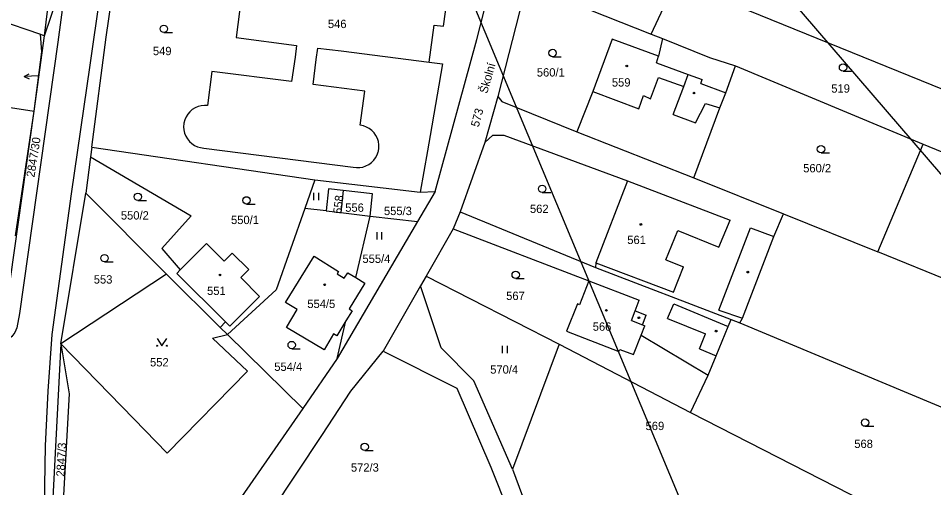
# Model space of a CAD drawing. Extents: x -558358 to -557517, y -1073785 to -1073189.
# Drawn here: x -558184.5 to -557998, y -1073651.5 to -1073555.9 of the extents above; entities that cross this region are included whole.
import ezdxf

# ---------------------------------------------------------------- set-up
doc = ezdxf.new("R2010")
doc.units = 0
for name, color, linetype in [('Hranice parcel', 7, 'Continuous'), ('Parcelní čísla', 7, 'Continuous'), ('Pop  PČ popisy', 7, 'Continuous'), ('Vnitřní kresba', 7, 'Continuous'), ('Vrstva 28', 7, 'Continuous'), ('Značky budov', 7, 'Continuous'), ('Značky kultur', 7, 'Continuous')]:
    doc.layers.add(name, color=color, linetype=linetype)

msp = doc.modelspace()

# ---------------------------------------------------------------- linework, layer by layer
at = {"layer": 'Hranice parcel'}
for p, q in [((-558179.14, -1073559.41), (-558177.37, -1073544.49)), ((-558179.14, -1073559.41), (-558174.43, -1073545.49)), ((-558174.43, -1073545.49), (-558176.44, -1073560.75)), ((-558210.55, -1073548.74), (-558179.99, -1073559.12)), ((-558080.96, -1073549.01), (-558086.83, -1073571.83)), ((-558080.96, -1073549.01), (-558055.56, -1073559.09)), ((-558181.3, -1073574.78), (-558179.14, -1073559.41)), ((-558179.99, -1073559.12), (-558179.14, -1073559.41)), ((-558055.56, -1073559.09), (-558053.26, -1073559.97)), ((-558038.36, -1073565.55), (-558000.16, -1073581.51)), ((-558219.67, -1073569.09), (-558181.3, -1073574.78)), ((-558086.83, -1073571.83), (-558089.47, -1073581.15)), ((-558187.72, -1073620.52), (-558181.3, -1073574.78)), ((-558185.06, -1073600.21), (-558181.3, -1073574.78)), ((-558070.72, -1073578.99), (-558046.87, -1073588.38)), ((-558089.47, -1073581.15), (-558094.5, -1073595.31)), ((-558009.36, -1073603.49), (-558000.16, -1073581.51)), ((-558000.16, -1073581.51), (-557977.41, -1073591.02)), ((-558169.56, -1073582.12), (-558169.81, -1073584.08)), ((-558169.56, -1073582.12), (-558124.1, -1073588.8)), ((-558146.72, -1073582.31), (-558116.26, -1073586.22)), ((-558169.81, -1073584.08), (-558170.74, -1073591.52)), ((-558124.1, -1073588.8), (-558126.13, -1073594.62)), ((-558124.1, -1073588.8), (-558102.62, -1073591.27)), ((-558046.87, -1073588.38), (-558028.58, -1073595.68)), ((-558118.29, -1073590.98), (-558118.81, -1073595.47)), ((-558099.6, -1073591.18), (-558103.17, -1073597.28)), ((-558102.62, -1073591.27), (-558099.6, -1073591.18)), ((-558175.82, -1073622.18), (-558170.74, -1073591.52)), ((-558154.32, -1073608.02), (-558170.74, -1073591.52)), ((-558121.8, -1073595.12), (-558126.13, -1073594.62)), ((-558121.8, -1073595.12), (-558118.81, -1073595.47)), ((-558118.81, -1073595.47), (-558112.83, -1073596.16)), ((-558115.73, -1073608.72), (-558112.83, -1073596.16)), ((-558112.83, -1073596.16), (-558103.17, -1073597.28)), ((-558094.5, -1073595.31), (-558095.93, -1073598.78)), ((-558094.5, -1073595.31), (-558066.88, -1073606.68)), ((-558028.58, -1073595.68), (-558009.36, -1073603.49)), ((-558103.17, -1073597.28), (-558119.53, -1073625.2)), ((-558095.93, -1073598.78), (-558101.44, -1073608.4)), ((-558155.28, -1073602.76), (-558151.5, -1073607.15)), ((-557981.3, -1073614.89), (-558009.36, -1073603.49)), ((-558154.32, -1073608.02), (-558175.82, -1073622.18)), ((-558143.35, -1073618.87), (-558154.32, -1073608.02)), ((-558066.88, -1073606.68), (-558039.3, -1073617.26)), ((-558101.44, -1073608.4), (-558102.56, -1073610.37)), ((-558101.44, -1073608.4), (-558074.34, -1073622.3)), ((-558102.56, -1073610.37), (-558110.18, -1073623.69)), ((-558039.3, -1073617.26), (-558037.5, -1073617.95)), ((-558142.28, -1073617.72), (-558143.35, -1073618.87)), ((-558141.92, -1073620.28), (-558143.35, -1073618.87)), ((-558119.53, -1073625.2), (-558117.76, -1073617.53)), ((-558126.57, -1073635.37), (-558141.92, -1073620.28)), ((-558074.34, -1073622.3), (-558083.83, -1073647.78)), ((-558074.34, -1073622.3), (-558047.53, -1073636.2)), ((-558119.53, -1073625.2), (-558126.57, -1073635.37)), ((-558047.53, -1073636.2), (-558043.97, -1073628.57)), ((-558083.83, -1073647.78), (-558091.67, -1073629.76)), ((-558126.57, -1073635.37), (-558152.59, -1073672.96)), ((-558047.53, -1073636.2), (-557987.38, -1073666.93)), ((-558083.83, -1073647.78), (-558081.75, -1073653.27))]:
    msp.add_line(p, q, dxfattribs=at)
for points in [[(-558086.19, -1073392.25), (-558100.56, -1073410.01), (-558117.51, -1073431.08), (-558131.78, -1073449.27), (-558138.48, -1073457.68), (-558143.38, -1073464.02), (-558146.99, -1073468.89), (-558150.46, -1073473.83), (-558152.02, -1073476.41), (-558154.26, -1073480.97), (-558156.46, -1073486.6), (-558158.91, -1073494.31), (-558160.3, -1073500.48), (-558162.16, -1073510.4), (-558165.76, -1073536.46), (-558169.94, -1073565.43), (-558173.74, -1073591.61), (-558177.66, -1073620.33), (-558178.51, -1073631.87), (-558179.02, -1073643), (-558179.24, -1073655.12), (-558179.45, -1073666.94), (-558179.49, -1073675.4)], [(-558169.56, -1073582.12), (-558166.59, -1073559.69), (-558162.5, -1073531.6)], [(-558137.04, -1073535.13), (-558138.34, -1073545.94), (-558140.1, -1073559.78), (-558127.81, -1073561.38), (-558128.13, -1073563.82), (-558128.85, -1073568.77)], [(-558099.6, -1073591.18), (-558091.09, -1073560.2), (-558086.54, -1073542.34)], [(-558055.56, -1073559.09), (-558052.02, -1073551.52), (-558051, -1073549.15), (-558050.57, -1073548.21)], [(-557977.41, -1073591.02), (-557981.5, -1073577.12), (-557984.25, -1073575.17), (-558047.33, -1073549.53)], [(-558181.3, -1073574.78), (-558179.75, -1073562.68), (-558179.99, -1073559.12)], [(-558176.44, -1073560.75), (-558184.28, -1073616.01), (-558184.84, -1073618.94), (-558185.24, -1073619.89), (-558185.86, -1073620.72), (-558186.64, -1073621.38)], [(-558053.26, -1073559.97), (-558054.09, -1073563.56), (-558063.5, -1073560.11), (-558067.45, -1073570.76), (-558070.72, -1073578.99)], [(-558053.26, -1073559.97), (-558043.68, -1073563.84), (-558038.36, -1073565.55)], [(-558124.4, -1073569.34), (-558123.84, -1073564.23), (-558123.49, -1073561.94), (-558118.73, -1073562.49), (-558100.77, -1073564.79), (-558098.05, -1073565.18), (-558100.59, -1073579.72), (-558101.17, -1073582.9), (-558102.62, -1073591.27)], [(-558128.85, -1073568.77), (-558145.05, -1073566.7), (-558145.94, -1073573.66)], [(-558046.87, -1073588.38), (-558041.59, -1073574.1), (-558040.35, -1073571.05), (-558038.36, -1073565.55)], [(-558114.83, -1073577.66), (-558113.93, -1073570.69), (-558124.4, -1073569.34)], [(-558086.83, -1073571.83), (-558085.98, -1073572.82), (-558070.72, -1073578.99)], [(-558145.94, -1073573.66), (-558146.6, -1073573.63), (-558147.25, -1073573.7), (-558147.89, -1073573.86), (-558148.5, -1073574.12), (-558149.06, -1073574.47), (-558149.56, -1073574.9), (-558149.98, -1073575.4), (-558150.33, -1073575.96), (-558150.59, -1073576.57), (-558150.76, -1073577.21), (-558150.78, -1073577.3), (-558150.83, -1073577.96), (-558150.78, -1073578.62), (-558150.63, -1073579.26), (-558150.39, -1073579.87), (-558150.06, -1073580.44), (-558149.64, -1073580.95), (-558149.15, -1073581.4), (-558148.6, -1073581.76), (-558148.01, -1073582.04), (-558147.37, -1073582.22), (-558146.72, -1073582.31)], [(-558116.26, -1073586.22), (-558115.61, -1073586.3), (-558114.95, -1073586.29), (-558114.3, -1073586.17), (-558113.68, -1073585.96), (-558113.09, -1073585.66), (-558112.56, -1073585.27), (-558112.09, -1073584.8), (-558111.7, -1073584.27), (-558111.4, -1073583.69), (-558111.18, -1073583.06), (-558111.15, -1073582.95), (-558111.05, -1073582.3), (-558111.05, -1073581.64), (-558111.15, -1073580.99), (-558111.35, -1073580.36), (-558111.64, -1073579.77), (-558112.02, -1073579.22), (-558112.47, -1073578.75), (-558112.99, -1073578.34), (-558113.57, -1073578.02), (-558114.19, -1073577.79), (-558114.83, -1073577.66)], [(-558089.47, -1073581.15), (-558087.83, -1073579.66), (-558085.58, -1073579.68), (-558060.36, -1073588.97), (-558066.81, -1073605.67), (-558066.88, -1073606.68)], [(-558169.81, -1073584.08), (-558149.27, -1073596.11), (-558155.28, -1073602.76)], [(-558118.29, -1073590.98), (-558121.28, -1073590.64), (-558121.8, -1073595.12)], [(-558112.83, -1073596.16), (-558112.31, -1073591.67), (-558118.29, -1073590.98)], [(-558126.13, -1073594.62), (-558131.94, -1073611.23), (-558141.92, -1073620.28)], [(-558037.5, -1073617.95), (-558036.99, -1073617), (-558030.56, -1073600.34), (-558028.58, -1073595.68)], [(-558095.93, -1073598.78), (-558068.28, -1073609.38), (-558070.18, -1073614.23), (-558070.6, -1073614.06), (-558072.8, -1073619.63), (-558062.12, -1073623.77), (-558061.94, -1073623.36), (-558059.17, -1073624.37), (-558057.59, -1073620.43), (-558043.97, -1073628.57)], [(-558142.28, -1073617.72), (-558141.4, -1073618.59), (-558135.35, -1073612.55), (-558139.15, -1073608.7), (-558137.51, -1073607.05), (-558140.91, -1073603.7), (-558142.57, -1073605.38), (-558146.16, -1073601.75), (-558151.5, -1073607.15)], [(-558117.76, -1073617.53), (-558119.58, -1073620.56), (-558120.26, -1073620.18), (-558122.2, -1073623.43), (-558129.88, -1073618.85), (-558127.67, -1073615.2), (-558130.05, -1073613.78), (-558124.22, -1073604.32), (-558119.25, -1073607.46), (-558119.52, -1073607.94), (-558118.12, -1073608.84), (-558117.4, -1073607.72), (-558115.73, -1073608.72)], [(-558151.5, -1073607.15), (-558152.22, -1073607.87), (-558142.28, -1073617.72)], [(-558115.73, -1073608.72), (-558113.89, -1073609.83), (-558117.1, -1073615.05), (-558116.51, -1073615.45), (-558117.76, -1073617.53)], [(-558091.67, -1073629.76), (-558098.34, -1073623.01), (-558102.56, -1073610.37)], [(-558043.97, -1073628.57), (-558042.35, -1073624.63), (-558039.87, -1073618.65), (-558039.3, -1073617.26)], [(-558037.5, -1073617.95), (-557968.93, -1073646.57), (-557957.49, -1073653.98)], [(-558175.82, -1073622.18), (-558161, -1073637.48), (-558154.2, -1073644.46), (-558137.82, -1073627.75), (-558144.92, -1073621.06), (-558141.92, -1073620.28)], [(-558175.82, -1073622.18), (-558177.63, -1073656.22), (-558176.05, -1073666.5)], [(-558175.82, -1073622.18), (-558174.18, -1073632.38), (-558176.05, -1073666.5)], [(-558143.16, -1073671.79), (-558122.68, -1073640.91), (-558116.74, -1073631.82), (-558110.18, -1073623.69)], [(-558110.18, -1073623.69), (-558095.16, -1073631.27), (-558088.2, -1073647.35), (-558084.61, -1073656.37)]]:
    msp.add_lwpolyline(points, dxfattribs=at)
at = {"layer": 'Pop  PČ popisy'}
for p, q in [((-558183.31, -1073567.74), (-558182.33, -1073567.19)), ((-558180.31, -1073567.58), (-558183.31, -1073567.74)), ((-558183.31, -1073567.74), (-558182.28, -1073568.19))]:
    msp.add_line(p, q, dxfattribs=at)
at = {"layer": 'Vnitřní kresba'}
for p, q in [((-558097.85, -1073557.5), (-558097.04, -1073551.46)), ((-558100.77, -1073564.79), (-558099.8, -1073557.24)), ((-558099.8, -1073557.24), (-558097.85, -1073557.5)), ((-558054.51, -1073564.95), (-558054.09, -1073563.56)), ((-558054.51, -1073564.95), (-558048, -1073567.3)), ((-558055.72, -1073572.3), (-558054.04, -1073567.93)), ((-558054.04, -1073567.93), (-558048.94, -1073569.79)), ((-558048.94, -1073569.79), (-558048, -1073567.3)), ((-558048, -1073567.3), (-558045.17, -1073568.34)), ((-558045.48, -1073569.18), (-558045.17, -1073568.34)), ((-558067.45, -1073570.76), (-558058.09, -1073574.3)), ((-558051.08, -1073575.44), (-558048.94, -1073569.79)), ((-558045.48, -1073569.18), (-558040.35, -1073571.05)), ((-558058.09, -1073574.3), (-558057.1, -1073571.59)), ((-558057.1, -1073571.59), (-558055.72, -1073572.3)), ((-558046.52, -1073577.2), (-558044.47, -1073573.2)), ((-558044.47, -1073573.2), (-558041.59, -1073574.1)), ((-558051.08, -1073575.44), (-558046.52, -1073577.2)), ((-558060.36, -1073588.97), (-558039.44, -1073597)), ((-558041.81, -1073602.48), (-558039.44, -1073597)), ((-558041.75, -1073615.33), (-558035.32, -1073598.58)), ((-558035.32, -1073598.58), (-558030.56, -1073600.34)), ((-558052.58, -1073605.08), (-558050.15, -1073599.12)), ((-558050.15, -1073599.12), (-558041.81, -1073602.48)), ((-558066.81, -1073605.67), (-558051.04, -1073611.69)), ((-558052.58, -1073605.08), (-558049.01, -1073606.53)), ((-558051.04, -1073611.69), (-558049.01, -1073606.53)), ((-558068.28, -1073609.38), (-558058.04, -1073613.34)), ((-558058.85, -1073615.47), (-558058.04, -1073613.34)), ((-558059.56, -1073617.45), (-558058.85, -1073615.47)), ((-558058.85, -1073615.47), (-558056.6, -1073616.37)), ((-558052.22, -1073617.07), (-558050.97, -1073614.06)), ((-558050.97, -1073614.06), (-558039.87, -1073618.65)), ((-558041.75, -1073615.33), (-558036.99, -1073617)), ((-558057.32, -1073618.35), (-558056.6, -1073616.37)), ((-558052.22, -1073617.07), (-558044.49, -1073620.2)), ((-558059.56, -1073617.45), (-558057.32, -1073618.35)), ((-558057.59, -1073620.43), (-558056.83, -1073618.55)), ((-558057.32, -1073618.35), (-558056.83, -1073618.55)), ((-558045.71, -1073623.2), (-558044.49, -1073620.2)), ((-558045.71, -1073623.2), (-558042.35, -1073624.63))]:
    msp.add_line(p, q, dxfattribs=at)
at = {"layer": 'Vrstva 28'}
for p, q in [((-558150.5, -1073408.33), (-557941.76, -1073651.48)), ((-558150.16, -1073413.05), (-558044.9, -1073665.43))]:
    msp.add_line(p, q, dxfattribs=at)
at = {"layer": 'Značky budov'}
for centre in [(-558060.53, -1073565.58), (-558046.85, -1073571.1), (-558057.66, -1073597.88), (-558143.42, -1073608.17), (-558035.89, -1073607.59), (-558122.08, -1073610.17), (-558064.7, -1073615.39), (-558058.07, -1073616.9), (-558042.33, -1073619.61)]:
    msp.add_circle(centre, 0.175, dxfattribs=at)
at = {"layer": 'Značky kultur'}
for p, q in [((-558154.86, -1073558.76), (-558153.11, -1073558.76)), ((-558075.65, -1073563.69), (-558073.9, -1073563.69)), ((-558016.47, -1073566.66), (-558014.72, -1073566.66)), ((-558020.96, -1073583.29), (-558019.21, -1073583.29)), ((-558160.14, -1073592.98), (-558158.39, -1073592.98)), ((-558124.27, -1073592.93), (-558124.27, -1073591.43)), ((-558123.27, -1073592.93), (-558123.27, -1073591.43)), ((-558077.78, -1073591.38), (-558076.03, -1073591.38)), ((-558138.02, -1073593.72), (-558136.27, -1073593.72)), ((-558111.42, -1073600.94), (-558111.42, -1073599.44)), ((-558110.42, -1073600.94), (-558110.42, -1073599.44)), ((-558166.95, -1073605.5), (-558165.2, -1073605.5)), ((-558083.17, -1073608.9), (-558081.42, -1073608.9)), ((-558085.87, -1073624.09), (-558085.87, -1073622.59)), ((-558084.87, -1073624.09), (-558084.87, -1073622.59)), ((-558128.81, -1073623.2), (-558127.06, -1073623.2)), ((-558011.98, -1073639.01), (-558010.23, -1073639.01)), ((-558113.93, -1073643.96), (-558112.18, -1073643.96))]:
    msp.add_line(p, q, dxfattribs=at)
msp.add_lwpolyline([(-558156.24, -1073621.11), (-558155.24, -1073622.61), (-558154.24, -1073621.11)], dxfattribs=at)
for centre, radius in [((-558154.86, -1073558.01), 0.75), ((-558075.65, -1073562.94), 0.75), ((-558016.47, -1073565.91), 0.75), ((-558020.96, -1073582.54), 0.75), ((-558077.78, -1073590.63), 0.75), ((-558160.14, -1073592.23), 0.75), ((-558138.02, -1073592.97), 0.75), ((-558166.95, -1073604.75), 0.75), ((-558083.17, -1073608.15), 0.75), ((-558156.24, -1073622.61), 0.1), ((-558154.24, -1073622.61), 0.1), ((-558128.81, -1073622.45), 0.75), ((-558011.98, -1073638.26), 0.75), ((-558113.93, -1073643.21), 0.75)]:
    msp.add_circle(centre, radius, dxfattribs=at)

# ---------------------------------------------------------------- texts
at = {"layer": 'Parcelní čísla'}
for s, p in [('546', (-558121.43, -1073557.86)), ('549', (-558157.09, -1073563.38)), ('560/1', (-558078.86, -1073567.74)), ('559', (-558063.57, -1073569.78)), ('519', (-558018.87, -1073571.02)), ('560/2', (-558024.59, -1073587.26)), ('556', (-558117.9, -1073595.3)), ('555/3', (-558110.01, -1073595.97)), ('562', (-558080.26, -1073595.54)), ('550/2', (-558163.61, -1073596.88)), ('550/1', (-558141.17, -1073597.8)), ('561', (-558060.43, -1073601.87)), ('555/4', (-558114.39, -1073605.72)), ('553', (-558169.13, -1073609.93)), ('551', (-558146.05, -1073612.25)), ('567', (-558085.11, -1073613.27)), ('554/5', (-558125.62, -1073614.91)), ('566', (-558067.47, -1073619.54)), ('552', (-558157.67, -1073626.81)), ('554/4', (-558132.36, -1073627.72)), ('570/4', (-558088.36, -1073628.28)), ('569', (-558056.7, -1073639.78)), ('568', (-558014.18, -1073643.43)), ('572/3', (-558116.74, -1073648.25))]:
    msp.add_text(s, height=1.7, dxfattribs=at).set_placement(p)
for s, rotation, p in [('573', 75, (-558090.71, -1073578.15)), ('2847/30', 81, (-558181.23, -1073588.36)), ('558', 83, (-558118.7, -1073595.8)), ('2847/3', 87, (-558175.1, -1073649.31))]:
    msp.add_text(s, height=1.7, rotation=rotation, dxfattribs=at).set_placement(p)
at = {"layer": 'Pop  PČ popisy'}
msp.add_text('Školní', height=1.7, rotation=74, dxfattribs=at).set_placement((-558088.99, -1073571.32))

doc.saveas('drawing.dxf')
